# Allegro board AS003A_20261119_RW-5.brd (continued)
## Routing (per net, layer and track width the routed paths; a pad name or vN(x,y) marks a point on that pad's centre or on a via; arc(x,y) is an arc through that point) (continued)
D11006: length 247.7
  L03_DIG w0.096: D110.06 407.82,349.4 407.36,349.4 406.47,348.51 406.47,347.48 407.73,346.22 407.73,324.49 405.35,322.1 405.35,310.08 410.6,304.83 410.6,237.77 409.11,236.29 407.56,236.29 406.21,237.64 406.21,244.38 405.24,245.35 403.7,245.35 392.39,234.05 392.39,230.6 383.49,221.7 377.13,221.7 375.92,222.92 330.29,222.92 327.9,220.53 318.25,220.53 316.41,218.69 305.81,218.69 305.37,218.25 303.95,218.25 303.93,218.23 303.91,218.23
  L03_DIG w0.102: 303.91,218.23 v1(303.23,218.23)
D11007: length 228.4
  L07_DIG w0.081: D110.07 407.69,351.77 407.69,342.27 408.37,341.59 422.56,341.59 423.28,340.86 423.28,328.65 418.08,323.45 418.08,298.32 411.98,292.23 396.71,292.23 359.06,254.58 320.02,254.58 300.95,235.51 300.95,232.8 298.03,229.88 298.03,227.71
  L07_DIG w0.102: v1(297.63,223.83) 298.03,224.23 298.03,227.71
D11008: length 247.7
  L03_DIG w0.096: 303.91,218.63 303.93,218.63 303.95,218.61 305.22,218.61 305.66,219.06 316.26,219.06 318.1,220.89 327.74,220.89 330.14,223.29 376.07,223.29 377.29,222.07 383.34,222.07 392.02,230.75 392.02,234.2 403.54,245.72 405.39,245.72 406.58,244.53 406.58,237.79 407.71,236.66 408.96,236.66 410.23,237.93 410.23,304.68 404.98,309.93 404.98,322.26 407.36,324.64 407.36,346.06 406.1,347.33 406.1,348.28 D110.08
  L03_DIG w0.102: 303.91,218.63 302.83,218.63 v1(302.43,218.23)
D11009: length 204.1
  L30_DIG w0.081: 303.91,213.83 304.95,213.83 306.15,215.04 311.67,215.04 311.97,214.74 318.14,214.74 320.09,212.79 328.92,212.79 343.34,227.2 343.34,249.14 347.94,253.74 356.42,253.74 389.6,286.93 389.6,301.7 400.13,312.22 400.13,351.87 D110.09
  L30_DIG w0.102: 303.91,213.83 302.03,213.83 v1(301.63,214.23)
D11010: length 257.7
  L03_DIG w0.096: 304.3,220.65 305.64,220.65 305.87,220.42 315.54,220.42 317.14,222.03 322.45,222.03 323.87,223.45 323.87,250.58 331.92,258.63 400.22,258.63 401.32,259.73 401.32,261.39 400.09,262.62 381.07,262.62 379.92,263.77 379.92,266.18 381.22,267.48 393.73,267.48 395.4,269.15 395.4,323.41 397.65,325.66 397.65,346.01 396.45,347.22 396.45,348.84 397.11,349.5 397.76,349.5 D110.10
  L03_DIG w0.102: 304.3,220.65 304.29,220.64 304.01,220.64 304,220.63 v1(303.23,220.63)
D11011: length 200.1
  L30_DIG w0.081: 303.91,215.43 304.64,215.43 305.95,216.74 317.73,216.74 324.05,223.05 330.87,223.05 333.19,225.38 333.19,253.56 336.5,256.87 354.42,256.87 386.27,288.72 386.27,305.14 395.13,314 395.13,351.95 D110.11
  L30_DIG w0.102: 303.91,215.43 302.03,215.43 v1(301.63,215.83)
D11012: length 257.7
  L03_DIG w0.096: D110.12 396.08,348.14 396.08,347.06 397.28,345.86 397.28,325.81 395.03,323.56 395.03,269.31 393.58,267.85 381.07,267.85 379.55,266.33 379.55,263.61 380.92,262.25 399.94,262.25 400.95,261.24 400.95,259.89 400.07,259 331.77,259 323.5,250.74 323.5,223.6 322.29,222.39 316.99,222.39 315.38,220.79 306.03,220.79 305.79,221.02 304.3,221.02
  L03_DIG w0.102: 304.3,221.02 304.01,221.02 303.99,221.03 302.83,221.03 v1(302.43,220.63)
D11013: length 195.3
  L30_DIG w0.081: 303.91,217.03 304.48,217.03 305.93,218.48 316.71,218.48 322.99,224.76 322.99,254.43 328.22,259.65 352.15,259.65 383,290.5 383,307.18 389.87,314.06 389.87,351.77 D110.13
  L30_DIG w0.102: v1(301.63,217.43) 302.03,217.03 303.91,217.03
D11014: length 198.2
  L03_DIG w0.096: D110.14 387.11,349.01 387.11,347.13 386.48,346.51 378.16,346.51 375.06,343.41 375.06,270.46 365.84,261.25 331.04,261.25 320.45,250.66 320.45,239.56 321.78,238.23 321.78,233.55 320.01,231.77 320.01,226.91 315.32,222.22 305.53,222.22 305.15,221.85 303.95,221.85 303.93,221.83 303.91,221.83
  L03_DIG w0.102: v1(302.43,222.23) 302.83,221.83 303.91,221.83
D11015: length 282.4
  L30_DIG w0.081: D110.15 378.32,360.82 378.32,392.29 377.01,393.6 371.22,393.6 369.35,391.73 369.35,380.91 367.05,378.62 356.72,378.62 352.79,374.68 352.79,265.45 350.03,262.7 323,262.7 318.95,258.65 318.95,224.35 314.98,220.39 305.86,220.39 304.91,219.43 303.91,219.43
  L30_DIG w0.102: v1(301.63,219.83) 302.03,219.43 303.91,219.43
D11016: length 198.2
  L03_DIG w0.096: D110.16 384.69,349.37 386.17,349.37 386.74,348.81 386.74,347.29 386.33,346.88 378.01,346.88 374.69,343.56 374.69,270.61 365.69,261.61 330.89,261.61 320.08,250.81 320.08,239.41 321.41,238.08 321.41,233.7 319.64,231.93 319.64,227.06 315.17,222.59 305.37,222.59 305,222.21 303.95,222.21 303.93,222.23 303.91,222.23
  L03_DIG w0.102: 303.91,222.23 v1(303.23,222.23)
D11101: length 237.5
  L07_DIG w0.081: K6.4 322.29,215.85 331.17,215.85 337.56,222.24 363.64,222.24 373.56,232.16 373.56,253.87 401.82,282.13 417.05,282.13 426.22,291.3 426.22,321.09 430.41,325.28 430.41,364.61 D111.01
D11102: length 314.6
  L05_DIG w0.079: D111.02 416.55,368.29 416.55,367.75 416.98,367.33 421.46,367.33 423.64,369.51 423.64,374.16 424.78,375.3 426.45,375.3 427.4,374.35 427.4,331.64 416.59,320.82 416.59,242.73 414.27,240.41 393.3,240.41 391.5,242.22 374.81,242.22 372.2,244.83 358.67,244.83 353.56,249.94 343.4,249.94 335.86,257.48 329.99,257.48 323.46,250.95 323.46,222.67 319.41,218.62 305.7,218.62 305.12,218.04 304.14,218.04 303.93,217.83 303.91,217.83
  L05_DIG w0.102: v1(300.83,218.23) 301.23,217.83 303.91,217.83
D11103: length 257.9
  L07_DIG w0.081: 303.91,218.63 304.36,218.63 306.35,220.62 327.88,220.62 330.44,223.18 352.93,223.18 359.55,229.79 359.55,233.3 363.5,237.25 370.61,237.25 372.72,239.37 372.72,254.74 401.18,283.2 416.56,283.2 424.87,291.52 424.87,321.98 429.29,326.39 429.29,363.04 422.88,369.45 418.29,369.45 417.76,369.99 417.76,372.18 D111.03
  L07_DIG w0.102: v1(300.03,219.03) 300.43,218.63 303.91,218.63
D11104: length 314.6
  L05_DIG w0.079: D111.04 416.17,368.69 416.17,367.59 416.82,366.94 421.62,366.94 424.03,369.35 424.03,374 424.94,374.92 426.3,374.92 427.02,374.19 427.02,331.8 416.2,320.98 416.2,242.89 414.11,240.8 393.46,240.8 391.66,242.6 374.97,242.6 372.36,245.21 358.83,245.21 353.72,250.32 343.56,250.32 336.02,257.87 329.84,257.87 323.08,251.11 323.08,222.83 319.26,219 305.54,219 304.96,218.42 304.14,218.42 303.93,218.63 303.91,218.63
  L05_DIG w0.102: 303.91,218.63 300.43,218.63 v1(300.03,218.23)
D11105: length 257.7
  L07_DIG w0.081: D111.05 412.58,372.28 412.58,368.07 413.52,367.12 422.61,367.12 428.16,361.58 428.16,327 423.65,322.49 423.65,292.66 415.53,284.55 399.82,284.55 360.5,245.23 360.5,239.32 357.8,236.61 350.91,236.61 349.59,237.94 339.39,237.94 338.91,238.42 338.42,238.42 333.91,233.91 330.62,233.91 329.78,234.76 322.51,234.76 319.03,231.28 319.03,224.9 316.49,222.37 306.17,222.37 304.83,221.03 303.91,221.03
  L07_DIG w0.102: v1(300.03,221.43) 300.43,221.03 303.91,221.03
D11106: length 260.6
  L05_DIG w0.079: 303.91,220.23 303.93,220.23 304.14,220.44 316.37,220.44 319.4,223.47 319.4,250.59 330.29,261.49 411.02,261.49 412.14,262.6 412.14,267.22 411.13,268.22 405.79,268.22 405.37,268.64 405.37,366.13 406.42,367.18 406.42,368.32 D111.06
  L05_DIG w0.102: 303.91,220.23 301.23,220.23 v1(300.83,220.63)
D11107: length 233.2
  L30_DIG w0.081: D111.07 405.15,372.13 405.15,312.76 393.52,301.14 393.52,284.74 368.11,259.33 368.11,234.42 358.05,224.36 343.77,224.36 341.28,221.87 341.28,220.83 331.21,210.77 318.17,210.77 315.83,213.11 306.08,213.11 305.2,212.23 303.91,212.23
  L30_DIG w0.102: v1(301.63,212.63) 302.03,212.23 303.91,212.23
D11108: length 260.6
  L05_DIG w0.079: 303.91,221.03 303.93,221.03 304.14,220.82 316.21,220.82 319.02,223.62 319.02,250.75 330.14,261.87 410.86,261.87 411.75,262.76 411.75,267.06 410.98,267.84 405.63,267.84 404.99,268.48 404.99,366.29 406.03,367.34 406.03,368.67 D111.08
  L05_DIG w0.102: v1(300.03,220.63) 300.43,221.03 303.91,221.03
D11109: length 257.7
  L34_DIG w0.102: v1(299.23,220.63) 299.63,221.03 303.91,221.03
  L34_DIG w0.104: D111.09 400.12,372.18 400.12,325.96 411.4,314.68 411.4,241.83 406.41,236.84 393.28,236.84 380.77,224.32 377.86,224.32 377.39,223.85 332.06,223.85 330.46,222.25 306.26,222.25 305.04,221.03 303.91,221.03
D11110: length 266.2
  L05_DIG w0.079: 303.91,221.83 303.93,221.83 304.14,222.04 315.48,222.04 316.52,223.08 316.52,242.24 317.95,243.66 317.95,253.63 327.78,263.46 398.09,263.46 401.47,266.84 401.47,270.34 398.99,272.82 385.86,272.82 383.75,274.93 383.75,281.5 385.79,283.54 392.05,283.54 395.25,286.73 395.25,366.16 397.12,368.03 397.12,369.18 D111.10
  L05_DIG w0.102: 303.91,221.83 300.43,221.83 v1(300.03,222.23)
D11111: length 328.2
  L34_DIG w0.102: v1(299.23,221.43) 299.63,221.83 303.91,221.83
  L34_DIG w0.104: D111.11 394.65,371.79 394.65,326.22 400.89,319.99 400.89,263.5 402.61,261.78 405.27,261.78 406.52,263.02 406.52,295.73 407.47,296.68 408.49,296.68 409.47,295.7 409.47,243.2 404.72,238.44 392.7,238.44 380.75,226.49 360.84,226.49 359.09,224.73 331.53,224.73 330.35,223.55 317.05,223.55 316.23,222.72 306.07,222.72 305.17,221.83 303.91,221.83
D11112: length 266.2
  L05_DIG w0.079: 303.91,222.63 303.93,222.63 304.14,222.42 315.32,222.42 316.14,223.24 316.14,242.4 317.56,243.82 317.56,253.79 327.62,263.84 397.93,263.84 401.09,267 401.09,270.18 398.83,272.44 385.7,272.44 383.37,274.77 383.37,281.66 385.63,283.92 391.89,283.92 394.86,286.89 394.86,366.32 396.73,368.19 396.73,369.3 396.32,369.72 394.82,369.72 D111.12
  L05_DIG w0.102: 303.91,222.63 301.23,222.63 v1(300.83,222.23)
D11113: length 247.7
  L34_DIG w0.102: 303.91,223.03 v1(303.23,223.03)
  L34_DIG w0.104: D111.13 389.85,372.07 389.85,312.14 390.82,311.18 392.74,311.18 393.63,312.08 393.63,318.91 394.38,319.65 396.1,319.65 396.84,318.91 396.84,277.06 376.34,256.56 326.37,256.56 319.45,249.64 319.45,227.69 315.85,224.09 304.97,224.09 303.91,223.03
D11114: length 328.2
  L05_DIG w0.079: D111.14 386.1,368.32 386.1,367.48 385.47,366.85 379.1,366.85 375.47,370.48 375.47,416.09 372.26,419.3 355.21,419.3 352.39,416.48 352.39,314.44 350.57,312.62 309.19,312.62 307.71,311.14 307.71,244.16 305.37,241.82 305.37,225 304.81,224.44 304.14,224.44 303.93,224.23 303.91,224.23
  L05_DIG w0.102: v1(300.83,224.63) 301.23,224.23 303.91,224.23
D11115: length 250.4
  L34_DIG w0.102: v1(303.23,223.83) 303.91,223.83
  L34_DIG w0.104: D111.15 384.84,372.14 384.84,289.8 385.06,289.59 385.37,289.59 385.58,289.8 385.58,304.21 385.8,304.43 386.11,304.43 386.32,304.21 386.32,270.68 373.83,258.18 323.52,258.18 316.91,251.57 316.91,227.55 315.28,225.93 306.01,225.93 303.91,223.83
D11116: length 328.2
  L05_DIG w0.079: D111.16 385.71,368.67 385.71,367.64 385.31,367.23 379.26,367.23 375.86,370.64 375.86,416.25 372.42,419.68 355.05,419.68 352.01,416.64 352.01,314.6 350.41,313 309.03,313 307.33,311.3 307.33,244.32 304.98,241.98 304.98,225.16 304.65,224.82 304.14,224.82 303.93,225.03 303.91,225.03
  L05_DIG w0.102: v1(300.03,224.63) 300.43,225.03 303.91,225.03
D11201: length 279.5
  L05_DIG w0.079: v1(333.87,244.93) 334.39,244.93 334.56,245.1 334.56,245.46 334.34,245.68 333.49,245.68 333.14,245.33 333.14,243.58 334.45,242.26 340.27,242.26 345.32,237.22 345.32,235.62 348.36,232.57 375.92,232.57 376.85,233.5 390.64,233.5 394.73,237.59 418.18,237.59 424.06,243.47 424.06,323.09 429.02,328.06 429.02,392.05 423.47,397.61 420.22,397.61 418.38,395.77 418.38,394.98 418.52,394.85 420.49,394.85 D112.01
  BOTTOM w0.109: v1(333.87,244.93) 333.87,242.8 333.56,242.38 333.13,242.32 K2.6
D11202: length 289.9
  L30_DIG w0.081: 303.91,207.43 304.94,207.43 305.31,207.8 313.47,207.8 317.73,203.54 389.67,203.54 404.9,218.76 404.9,297.48 417.74,310.33 417.74,389.8 D112.02
  L30_DIG w0.102: 303.91,207.43 302.03,207.43 v1(301.63,207.83)
D11203: length 279.5
  L05_DIG w0.079: v1(333.87,246.82) 333.87,246.22 333.71,246.06 333.33,246.06 332.75,245.48 332.75,243.42 334.29,241.88 340.11,241.88 344.93,237.06 344.93,235.46 348.2,232.19 376.08,232.19 377.01,233.12 390.8,233.12 394.89,237.21 418.34,237.21 424.44,243.31 424.44,322.93 429.41,327.9 429.41,392.21 423.62,398 420.06,398 418,395.93 418,395.14 D112.03
  BOTTOM w0.109: v1(333.87,246.82) 333.87,248.95 333.56,249.37 333.13,249.43 K2.4
D11204: length 262.3
  L30_DIG w0.081: 303.91,209.83 313.83,209.83 316.9,206.76 340.81,206.76 354.1,220.06 365.92,220.06 375,229.14 375,259.03 400.26,284.29 400.26,297.92 412.76,310.42 412.76,389.9 D112.04
  L30_DIG w0.102: 303.91,209.83 302.03,209.83 v1(301.63,210.23)
D11205: length 315.5
  L05_DIG w0.079: v1(333.87,227.66) 334.46,227.66 334.59,227.79 334.59,228.29 334.48,228.41 333.49,228.41 333.19,228.1 333.19,225.87 334.67,224.39 360.29,224.39 367.97,216.71 418.03,216.71 427.4,226.08 427.4,310.62 426.01,312.02 426.01,320.93 433.02,327.94 433.02,391.55 424.81,399.76 411.95,399.76 408.19,396 408.19,395.29 408.6,394.88 410.3,394.88 D112.05
  BOTTOM w0.109: v1(333.87,227.66) 333.87,225.52 333.56,225.11 333.13,225.05 K1.6
D11206: length 255.2
  L30_DIG w0.081: D112.06 407.61,389.83 407.61,312.4 395.85,300.63 395.85,285.08 371.22,260.45 371.22,231.36 363.14,223.29 350.16,223.29 344,217.12 340.05,217.12 332.86,209.94 317.34,209.94 315.24,212.04 305.68,212.04 305.07,211.43 303.91,211.43
  L30_DIG w0.102: 303.91,211.43 302.03,211.43 v1(301.63,211.83)
D11207: length 315.5
  L05_DIG w0.079: D112.07 407.8,395.1 407.8,396.16 411.79,400.14 424.97,400.14 433.4,391.71 433.4,327.78 426.39,320.77 426.39,312.18 427.79,310.78 427.79,225.92 418.19,216.33 367.81,216.33 360.13,224.01 334.51,224.01 332.8,225.71 332.8,228.26 333.33,228.79 333.71,228.79 333.87,228.95 v1(333.87,229.54)
  BOTTOM w0.109: K1.4 333.13,232.15 333.56,232.09 333.87,231.68 v1(333.87,229.54)
D11208: length 245.4
  L30_DIG w0.081: 303.91,213.03 305.07,213.03 305.86,213.82 317.77,213.82 319.71,211.88 329.87,211.88 343.33,225.34 353.44,225.34 360.64,232.53 360.64,255.48 391.33,286.17 391.33,300.93 402.67,312.27 402.67,389.97 D112.08
  L30_DIG w0.102: v1(301.63,213.43) 302.03,213.03 303.91,213.03
D11209: length 240.3
  L32_DIG w0.081: 298.83,227.71 298.83,228.45 297.67,229.61 297.67,233.29 321.69,257.31 371.55,257.31 400.12,285.88 400.12,392.5 D112.09
  L32_DIG w0.102: 298.83,227.71 298.83,226.63 v1(298.43,226.23)
D11210: length 242.8
  L30_DIG w0.081: 303.91,214.63 304.82,214.63 305.78,215.59 318.31,215.59 318.79,216.07 329.71,216.07 334.25,220.61 334.25,251.86 338.13,255.74 355.56,255.74 387.89,288.07 387.89,303.88 397.6,313.59 397.6,389.98 D112.10
  L30_DIG w0.102: 303.91,214.63 302.03,214.63 v1(301.63,215.03)
D11211: length 240.5
  L32_DIG w0.081: 297.23,227.71 297.23,228.19 296.67,228.75 296.67,234.46 320.69,258.47 368.88,258.47 394.94,284.53 394.94,392.4 D112.11
  L32_DIG w0.102: 297.23,227.71 297.23,223.43 v1(297.63,223.03)
D11212: length 235.4
  L30_DIG w0.081: 303.91,216.23 304.37,216.23 305.54,217.4 316.95,217.4 324.16,224.61 324.16,253.17 329.14,258.15 352.84,258.15 384.9,290.2 384.9,306.31 392.47,313.89 392.47,389.93 D112.12
  L30_DIG w0.102: v1(301.63,216.63) 302.03,216.23 303.91,216.23
D11213: length 221.4
  L32_DIG w0.081: K3.4 313.82,259.71 364.64,259.71 389.93,284.99 389.93,392.47 D112.13
D11214: length 232.6
  L30_DIG w0.081: D112.14 387.58,390.12 387.58,314.38 381.35,308.15 381.35,291.64 351.23,261.52 323.78,261.52 319.94,257.68 319.94,223.7 315.43,219.19 305.54,219.19 304.98,218.63 303.91,218.63
  L30_DIG w0.102: v1(301.63,219.03) 302.03,218.63 303.91,218.63
D11215: length 230.1
  L32_DIG w0.081: D112.15 384.96,392.58 384.96,284.65 361.43,261.13 299.88,261.13 290.55,251.79 290.55,247.48 K4.4
D11216: length 244
  L32_DIG w0.081: D112.16 379.54,387.16 379.54,284.48 357.15,262.09 294.42,262.09 283.15,250.82 283.15,239.87 284.43,238.59 284.43,227.71
  L32_DIG w0.102: v1(284.03,226.23) 284.43,226.63 284.43,227.71
D11301: length 153
  L09_DIG w0.079: v3(268.73,275.54) 268.73,276.96 268.57,277.11 268.19,277.11 267.67,277.63 267.67,304.83 265.93,306.57 265.93,315.86 271.22,321.15 283.54,321.15 287.45,325.06 350.15,325.06 352.23,327.15 352.23,334.68 350.48,336.43 346.6,336.43 345.33,335.15 345.33,334.73 346.2,333.86 346.86,333.86 D113.01
  BOTTOM w0.117: R144.2 v3(268.73,275.54)
D11302: length 157.1
  L07_DIG w0.079: v3(281.85,275.54) 281.85,276.96 282.01,277.11 282.39,277.11 283.04,277.76 283.04,297 267.15,312.89 261.01,312.89 259.88,314.02 259.88,316.02 260.73,316.87 275.27,316.87 284.01,308.13 328.97,308.13 343.1,322.25 343.1,327.86 D113.02
  BOTTOM w0.117: R138.2 v3(281.85,275.54)
D11303: length 153
  L09_DIG w0.079: D113.03 344.95,334.79 344.95,335.31 346.44,336.81 350.64,336.81 352.61,334.84 352.61,326.99 350.31,324.68 287.61,324.68 283.7,320.77 271.38,320.77 266.32,315.7 266.32,306.73 268.06,304.99 268.06,277.79 268.35,277.5 268.57,277.5 268.73,277.65 v3(268.73,279.06)
  BOTTOM w0.117: R143.2 v3(268.73,279.06)
D11304: length 157.1
  L07_DIG w0.079: v3(281.85,279.06) 281.85,277.65 282.01,277.5 282.23,277.5 282.65,277.92 282.65,296.84 266.99,312.5 260.85,312.5 259.5,313.86 259.5,316.18 260.57,317.25 275.43,317.25 284.17,308.51 328.81,308.51 342.72,322.41 342.72,328.92 342.42,329.22 341.34,329.22 D113.04
  BOTTOM w0.117: R137.2 v3(281.85,279.06)
D11305: length 153
  L09_DIG w0.079: v3(283.97,275.54) 283.97,276.96 283.81,277.11 283.43,277.11 282.8,277.74 282.8,312.9 292.75,322.85 351.48,322.85 354.94,326.31 354.94,336.57 352.79,338.72 338.38,338.72 335.29,335.63 335.29,334.45 335.98,333.76 336.8,333.76 D113.05
  BOTTOM w0.117: R140.2 v3(283.97,275.54)
D11306: length 157.1
  L07_DIG w0.079: v3(266.61,275.54) 266.61,276.96 266.77,277.11 267.15,277.11 267.75,277.71 267.75,298.25 255.62,310.38 249.65,310.38 247.38,312.65 247.38,317.08 249.18,318.88 279.41,318.88 287.03,311.26 320.68,311.26 332.93,323.52 332.93,327.85 D113.06
  BOTTOM w0.117: R141.2 v3(266.61,275.54)
D11307: length 153
  L09_DIG w0.079: v3(283.97,279.06) 283.97,277.65 283.81,277.5 283.59,277.5 283.18,277.9 283.18,312.74 292.91,322.47 351.63,322.47 355.32,326.15 355.32,336.73 352.95,339.1 338.22,339.1 334.91,335.79 334.91,334.91 D113.07
  BOTTOM w0.117: R139.2 v3(283.97,279.06)
D11308: length 157.1
  L07_DIG w0.079: v3(266.61,279.06) 266.61,277.65 266.77,277.5 266.99,277.5 267.36,277.87 267.36,298.09 255.46,309.99 249.5,309.99 247,312.49 247,317.24 249.02,319.26 279.57,319.26 287.19,311.65 320.52,311.65 332.55,323.68 332.55,328.93 332.22,329.25 331.15,329.25 D113.08
  BOTTOM w0.117: R142.2 v3(266.61,279.06)
D11309: length 153
  L09_DIG w0.079: D113.09 326.4,334 326.4,334.89 322.12,339.17 288.4,339.17 274.36,325.13 240.48,325.13 231.8,316.45 231.8,302.58 237.21,297.17 237.21,277.61 237.71,277.11 238.09,277.11 238.25,276.96 v3(238.25,275.54)
  BOTTOM w0.117: R152.2 v3(238.25,275.54)
D11310: length 157.1
  L07_DIG w0.079: D113.10 322.77,327.85 322.77,326.24 318.32,321.79 235.61,321.79 232.38,318.56 232.38,310.85 235.57,307.67 245.41,307.67 252.55,300.52 252.55,277.75 251.91,277.11 251.53,277.11 251.37,276.96 v3(251.37,275.54)
  BOTTOM w0.117: R145.2 v3(251.37,275.54)
D11311: length 153
  L09_DIG w0.079: D113.11 323.98,334.14 325.69,334.14 326.01,334.46 326.01,334.73 321.96,338.79 288.56,338.79 274.52,324.75 240.64,324.75 232.19,316.29 232.19,302.74 237.6,297.33 237.6,277.77 237.87,277.5 238.09,277.5 238.25,277.65 v3(238.25,279.06)
  BOTTOM w0.117: R151.2 v3(238.25,279.06)
D11312: length 157.1
  L07_DIG w0.079: D113.12 321.08,329.16 322.17,329.16 322.39,328.94 322.39,326.4 318.16,322.17 235.46,322.17 232,318.71 232,310.69 235.41,307.28 245.25,307.28 252.16,300.37 252.16,277.91 251.75,277.5 251.53,277.5 251.37,277.65 v3(251.37,279.06)
  BOTTOM w0.117: R146.2 v3(251.37,279.06)
D11313: length 153
  L09_DIG w0.079: D113.13 316.02,334.22 316.02,335.17 314.35,336.84 292.11,336.84 278.68,323.41 240.91,323.41 233.39,315.9 233.39,303.73 235.4,301.72 249.58,301.72 252.36,298.94 252.36,277.7 252.95,277.11 253.33,277.11 253.49,276.96 v3(253.49,275.54)
  BOTTOM w0.117: R148.2 v3(253.49,275.54)
D11314: length 157.1
  L07_DIG w0.079: v3(236.13,275.54) 236.13,276.96 236.29,277.11 236.67,277.11 237.23,277.67 237.23,297.77 231.25,303.75 223.94,303.75 220.49,307.21 220.49,320.11 224.26,323.88 310.73,323.88 312.88,326.03 312.88,328.12 D113.14
  BOTTOM w0.117: R149.2 v3(236.13,275.54)
D11315: length 153
  L09_DIG w0.079: v3(253.49,279.06) 253.49,277.65 253.33,277.5 253.11,277.5 252.75,277.86 252.75,299.1 249.74,302.1 235.56,302.1 233.77,303.89 233.77,315.74 241.06,323.03 278.84,323.03 292.27,336.46 314.19,336.46 315.63,335.01 315.63,333.92 315.39,333.68 313.36,333.68 D113.15
  BOTTOM w0.117: R147.2 v3(253.49,279.06)
D11316: length 157.1
  L07_DIG w0.079: D113.16 310.9,329.18 311.63,329.18 312.49,328.31 312.49,326.19 310.57,324.27 224.1,324.27 220.1,320.27 220.1,307.05 223.78,303.37 231.09,303.37 236.84,297.61 236.84,277.83 236.51,277.5 236.29,277.5 236.13,277.65 v3(236.13,279.06)
  BOTTOM w0.117: R150.2 v3(236.13,279.06)
D11401: length 247.7
  L30_DIG w0.081: 303.91,221.03 305.11,221.03 307.26,223.18 307.26,229.05 306.36,229.96 306.36,239.27 307.72,240.63 307.72,289.39 311.23,292.91 347.04,292.91 347.29,292.66 347.29,292.36 347.11,292.19 313.72,292.19 313.51,291.98 313.51,291.68 313.72,291.47 347.81,291.47 349.31,292.98 349.31,325.48 346.75,328.05 346.75,351.83 D114.01
  L30_DIG w0.102: 303.91,221.03 302.03,221.03 v1(301.63,221.43)
D11402: length 282.4
  L03_DIG w0.096: 303.91,224.63 303.93,224.63 303.95,224.65 304.78,224.65 305.4,224.03 315.37,224.03 316.97,225.62 316.97,232.24 319.09,234.37 319.09,254.24 327.75,262.9 346.9,262.9 353.69,269.68 353.69,299.79 364.03,310.13 364.03,362.85 370.14,368.96 370.14,386.57 366.27,390.45 355.79,390.45 352.05,386.71 352.05,348.88 349.99,346.81 343.74,346.81 343.14,347.41 343.14,348.87 343.66,349.4 344.32,349.4 D114.02
  L03_DIG w0.102: 303.91,224.63 v1(303.23,224.63)
D11403: length 250.4
  L30_DIG w0.081: 303.91,223.43 304.75,224.27 304.75,290.55 312.06,297.86 330.92,297.86 331.13,297.65 331.13,297.36 330.92,297.15 315.03,297.15 314.83,296.95 314.83,296.65 315.05,296.43 341.35,296.43 343.76,298.84 343.76,322.12 343.97,322.33 344.27,322.33 344.48,322.12 344.48,299.1 344.68,298.9 344.98,298.9 345.19,299.12 345.19,322.74 341.73,326.2 341.73,351.89 D114.03
  L30_DIG w0.102: v1(301.63,223.83) 302.03,223.43 303.91,223.43
D11404: length 282.4
  L03_DIG w0.096: 303.91,225.03 303.93,225.03 303.95,225.01 304.93,225.01 305.55,224.39 315.22,224.39 316.6,225.77 316.6,232.4 318.72,234.52 318.72,254.39 327.59,263.26 346.75,263.26 353.32,269.83 353.32,299.94 363.67,310.29 363.67,363 369.77,369.11 369.77,386.42 366.12,390.08 355.95,390.08 352.42,386.55 352.42,348.72 350.14,346.44 343.59,346.44 342.77,347.26 342.77,348.11 D114.04
  L03_DIG w0.102: 303.91,225.03 302.83,225.03 v1(302.43,224.63)
D11405: length 234.1
  L30_DIG w0.081: 301.23,227.71 301.23,254.17 302.84,255.78 302.84,291.85 311.85,300.86 339.69,300.86 341.4,302.57 341.4,321.84 340.89,322.35 340.23,322.35 339.88,322 339.88,303.24 339.34,302.71 338.58,302.71 338.12,303.16 338.12,320.8 337.91,321.01 337.61,321.01 337.4,320.8 337.4,305.97 337.2,305.76 336.9,305.76 336.69,305.97 336.69,351.93 D114.05
  L30_DIG w0.102: 301.23,227.71 301.23,225.83 v1(301.63,225.43)
D11406: length 234.1
  L03_DIG w0.096: D114.06 333.71,348.95 333.71,346.65 334.16,346.21 334.16,326.23 335.89,324.49 337.7,324.49 339.5,322.69 339.5,319.68 338.31,318.49 315.57,318.49 314.67,317.59 314.67,315.51 315.48,314.69 360.56,314.69 361.85,313.4 361.85,311.29 360.1,309.54 352.23,309.54 338.81,296.11 338.81,275.2 332.39,268.79 323.8,268.79 305.49,250.47 305.49,226.56 304.78,225.85 303.95,225.85 303.93,225.83 303.91,225.83
  L03_DIG w0.102: v1(302.43,226.23) 302.83,225.83 303.91,225.83
D11407: length 198.2
  L30_DIG w0.081: 298.83,227.71 298.83,230.48 297.62,231.69 297.62,272.73 294.03,276.33 294.03,289.99 310.02,305.98 329.42,305.98 329.63,305.77 329.63,305.47 329.42,305.26 310.8,305.26 310.57,305.04 310.57,304.74 310.77,304.55 330.36,304.55 331.56,305.74 331.56,351.88 D114.07
  L30_DIG w0.102: 298.83,227.71 298.83,225.83 v1(299.23,225.43)
D11408: length 234.1
  L03_DIG w0.096: 303.91,226.23 303.93,226.23 303.95,226.21 304.63,226.21 305.12,226.71 305.12,250.63 323.65,269.15 332.24,269.15 338.44,275.36 338.44,296.27 352.08,309.91 359.95,309.91 361.48,311.44 361.48,313.24 360.4,314.32 315.33,314.32 314.3,315.35 314.3,317.74 315.42,318.86 338.16,318.86 339.13,319.83 339.13,322.54 337.54,324.12 335.74,324.12 333.79,326.08 333.79,346.06 333.35,346.5 333.35,348.92 332.91,349.35 331.37,349.35 D114.08
  L03_DIG w0.102: 303.91,226.23 v1(303.23,226.23)
D11409: length 149.7
  L30_DIG w0.081: 283.63,227.71 283.63,230.5 290.15,237.03 290.15,292.51 306.79,309.14 313.13,309.14 326.41,322.43 326.41,351.81 D114.09
  L30_DIG w0.102: 283.63,227.71 283.63,225.83 v1(284.03,225.43)
D11410: length 250.4
  L03_DIG w0.096: 301.23,227.71 301.23,227.73 301.01,227.95 301.01,251.58 305.26,255.82 305.26,291.03 306.73,292.5 332.65,292.5 333.81,293.67 333.81,296.71 332.11,298.41 297.82,298.41 296.21,300.01 296.21,303.25 297.89,304.92 330.15,304.92 333.57,308.35 333.57,310.71 331.81,312.48 314.83,312.48 312.25,315.06 312.25,318.03 315.4,321.19 317.87,321.19 321.51,324.84 321.51,345.94 323.59,348.02 323.59,348.99 D114.10
  L03_DIG w0.102: 301.23,227.71 301.23,225.95 301.11,225.83 300.43,225.83 v1(300.03,226.23)
D11411: length 206.2
  L30_DIG w0.081: 282.03,227.71 282.03,232.19 287.77,237.93 287.77,296.96 283.37,301.37 283.37,337.38 286.14,340.14 297.43,340.14 300.29,337.29 300.29,322.33 305.51,317.1 314.55,317.1 321.41,323.96 321.41,351.89 D114.11
  L30_DIG w0.102: v1(282.43,225.43) 282.03,225.83 282.03,227.71
D11412: length 250.4
  L03_DIG w0.096: D114.12 321.22,349.34 322.66,349.34 323.22,348.77 323.22,348.17 321.15,346.09 321.15,324.99 317.71,321.56 315.25,321.56 311.88,318.19 311.88,314.91 314.68,312.11 331.65,312.11 333.21,310.56 333.21,308.5 330,305.29 297.74,305.29 295.85,303.4 295.85,299.86 297.67,298.04 331.96,298.04 333.44,296.55 333.44,293.82 332.5,292.87 306.58,292.87 304.89,291.19 304.89,255.98 300.65,251.73 300.65,227.95 300.43,227.73 300.43,227.71
  L03_DIG w0.102: v1(300.83,226.23) 300.43,226.63 300.43,227.71
D11413: length 515.3
  L30_DIG w0.081: D114.13 316.48,352.04 316.48,325.37 310.95,319.85 307.56,319.85 304.72,322.68 304.72,347.76 299.15,353.33 299.15,402.5 293.59,408.06 293.59,417.8 292.67,418.72 279.94,418.72 279.52,419.15 279.52,420.08 280.03,420.6 295.42,420.6 295.92,421.09 295.92,421.85 295.15,422.62 247.15,422.62 246.82,422.28 246.82,420.8 247.1,420.52 276.31,420.52 276.53,420.3 276.53,420 276.33,419.8 247.45,419.8 247.25,419.61 247.25,419.31 247.47,419.08 277.86,419.08 280.65,416.3 280.65,298.9 283.01,296.54 283.01,236.15 279.63,232.77 279.63,227.71
  L30_DIG w0.102: 279.63,227.71 279.63,225.83 v1(280.03,225.43)
D11414: length 515.2
  L03_DIG w0.096: 281.82,228.21 281.82,232.74 289.28,240.2 289.28,320.41 277.56,332.12 277.56,420.88 282.39,425.7 299.23,425.7 304.73,420.2 304.73,409.03 301.25,405.56 281.34,405.56 279.82,404.04 279.82,401.1 281.04,399.89 302.27,399.89 303.72,398.44 303.72,394.79 302.2,393.28 282.15,393.28 280.97,392.09 280.97,334.12 282.42,332.67 284.72,332.67 286.07,334.02 286.07,386.8 287.51,388.25 291.41,388.25 292.85,386.8 292.85,350.28 296.68,346.46 311.71,346.46 312.62,347.37 312.62,348.18 D114.14
  L03_DIG w0.102: v1(281.63,226.23) 282.03,226.63 282.03,227.71 281.82,227.92 281.82,228.21
D11415: length 394.1
  L30_DIG w0.081: 277.75,223.57 277.24,224.08 277.24,413.89 274.92,416.2 232.57,416.2 230.14,418.63 230.14,422.62 232.83,425.31 299.32,425.31 304.15,420.48 304.15,361.33 D114.15
  L30_DIG w0.102: v1(280.03,223.83) 279.63,223.43 277.89,223.43 277.75,223.57
D11416: length 515.3
  L03_DIG w0.096: 281.45,228.21 281.45,232.89 288.91,240.35 288.91,320.26 277.19,331.97 277.19,421.03 282.24,426.07 299.38,426.07 305.1,420.36 305.1,408.88 301.41,405.19 281.5,405.19 280.19,403.89 280.19,401.26 281.19,400.26 302.42,400.26 304.09,398.59 304.09,394.64 302.35,392.91 282.31,392.91 281.34,391.94 281.34,334.27 282.58,333.03 284.57,333.03 285.7,334.17 285.7,386.95 287.36,388.61 291.56,388.61 293.22,386.95 293.22,350.44 296.83,346.82 311.56,346.82 312.26,347.52 312.26,348.14 D114.16
  L03_DIG w0.102: 281.45,228.21 281.44,228.2 281.44,227.92 281.23,227.71 281.23,226.63 v1(280.83,226.23)
D11501: length 198.2
  L34_DIG w0.102: v1(300.83,227.03) 300.83,227.71
  L34_DIG w0.104: D115.01 346.8,372.2 346.8,307.24 347.04,307.01 347.34,307.01 347.54,307.21 347.54,312.94 347.76,313.16 348.07,313.16 348.28,312.94 348.28,298.76 342.03,292.51 310.5,292.51 307.47,289.47 307.47,259.51 300.83,252.87 300.83,227.71
D11502: length 247.7
  L30_DIG w0.081: 303.91,222.63 304.13,222.63 305.55,224.05 305.55,243.58 306.72,244.75 306.72,289.75 310.8,293.84 342.87,293.84 343.08,294.05 343.08,294.34 342.87,294.55 313.83,294.55 313.63,294.75 313.63,295.05 313.85,295.27 343.08,295.27 347.06,299.25 347.06,324.16 344.21,327.01 344.21,369.61 D115.02
  L30_DIG w0.102: 303.91,222.63 302.03,222.63 v1(301.63,223.03)
D11503: length 198.2
  L34_DIG w0.102: v1(299.23,227.03) 299.23,227.71
  L34_DIG w0.104: 299.23,227.71 299.23,229.8 297.54,231.49 297.54,258.69 303.74,264.9 303.74,294.35 307.02,297.62 334.43,297.62 343.11,306.3 343.11,315.4 342.89,315.62 342.59,315.62 342.37,315.4 342.37,308.44 342.17,308.24 341.87,308.24 341.63,308.47 341.63,372.11 D115.03
D11504: length 250.4
  L30_DIG w0.081: D115.04 341.32,371.8 341.32,373.97 342.17,374.81 344.66,374.81 348.21,378.36 348.21,378.93 347.56,379.58 342.09,379.58 341.71,379.96 341.71,381.41 342.38,382.09 353.66,382.09 354.26,382.7 354.26,384.31 353.54,385.04 339.67,385.04 339.2,384.58 339.2,325.3 342.57,321.93 342.57,299.86 340.61,297.9 332.92,297.9 331.33,299.48 312.01,299.48 303.91,291.38 303.91,227.71
  L30_DIG w0.102: 303.91,227.71 303.91,224.57 303.57,224.23 302.03,224.23 v1(301.63,224.63)
D11505: length 181.2
  L34_DIG w0.102: 284.03,227.71 v1(284.03,227.03)
  L34_DIG w0.104: 284.03,227.71 284.03,231.18 290.8,237.95 290.8,252.47 292.03,253.7 292.03,297.88 295.92,301.77 317.29,301.77 336.58,321.06 336.58,372.14 D115.05
D11506: length 266.2
  L30_DIG w0.081: D115.06 336.34,371.9 336.34,385.63 335.98,385.98 334.83,385.98 334.35,385.5 334.35,311.36 334.14,311.15 333.84,311.15 333.63,311.36 333.63,320.03 333.42,320.24 333.13,320.24 332.92,320.03 332.92,308.65 333.97,307.59 333.97,303.96 331.92,301.91 313.12,301.91 312.94,302.08 312.94,302.38 313.19,302.62 331.37,302.62 331.58,302.83 331.58,303.13 331.37,303.34 311.85,303.34 298.74,290.23 298.74,282.15 301.51,279.38 301.51,275.56 299.05,273.09 299.05,264.44 300.18,263.3 300.18,228.97 299.63,228.42 299.63,227.71
  L30_DIG w0.102: v1(300.03,225.43) 299.63,225.83 299.63,227.71
D11507: length 178.8
  L32_DIG w0.081: 283.63,227.71 283.63,235.41 279.65,239.39 279.65,250.82 292.8,263.96 292.8,294.06 300.43,301.69 313.79,301.69 331.58,319.48 331.58,372.22 D115.07
  L32_DIG w0.102: 283.63,227.71 283.63,226.63 v1(283.23,226.23)
D11508: length 167.2
  L30_DIG w0.081: D115.08 329.03,369.67 329.03,320.99 315.54,307.51 308.85,307.51 292.79,291.45 292.79,275.7 294.2,274.29 294.2,233.02 298.03,229.2 298.03,227.71
  L30_DIG w0.102: v1(298.43,225.43) 298.03,225.83 298.03,227.71
D11509: length 369.7
  L32_DIG w0.081: 282.03,227.71 282.03,232.18 277.91,236.3 277.91,251.45 289.04,262.57 289.04,371.24 289.98,372.17 291.33,372.17 292.69,370.8 292.69,330.07 293.97,328.79 296.68,328.79 297.55,329.66 297.55,371.26 298.55,372.26 301.01,372.26 302.14,371.13 302.14,328.45 306.16,324.43 324.3,324.43 326.46,326.59 326.46,372.18 D115.09
  L32_DIG w0.102: v1(282.43,223.03) 282.03,223.43 282.03,227.71
D11510: length 414.8
  L05_DIG w0.079: D115.10 323.96,369.68 322.89,369.68 321.78,368.57 321.78,366.37 321.44,366.03 321.44,326.14 320.11,324.81 307.17,324.81 306.47,324.11 306.47,322.88 307.36,321.99 346.4,321.99 348.45,319.94 348.45,317.5 347.11,316.16 305.94,316.16 301.65,320.45 301.65,326.88 298.82,329.71 293.16,329.71 291.57,328.11 291.57,315.59 289.97,314 287.38,314 285.53,315.84 285.53,370.67 284.2,372.01 282.78,372.01 281.69,370.92 281.69,311.7 288.81,304.59 288.81,240.58 276.8,228.57 276.8,225.16 277.13,224.83 277.35,224.83
  L05_DIG w0.102: 277.35,224.83 277.64,224.83 277.84,225.03 280.43,225.03 v1(280.83,224.63)
D11511: length 169.5
  L30_DIG w0.081: 282.83,227.71 282.83,231.34 288.96,237.47 288.96,293.98 305.41,310.43 311.9,310.43 323.97,322.5 323.97,371.99 D115.11
  L30_DIG w0.102: v1(283.23,225.43) 282.83,225.83 282.83,227.71
D11512: length 414.8
  L05_DIG w0.079: D115.12 321.39,369.49 321.39,366.53 321.06,366.19 321.06,326.3 319.95,325.2 307.01,325.2 306.08,324.27 306.08,322.72 307.2,321.6 346.24,321.6 348.07,319.78 348.07,317.65 346.95,316.54 306.1,316.54 302.03,320.61 302.03,327.04 298.98,330.09 293.01,330.09 291.18,328.27 291.18,315.75 289.81,314.38 287.54,314.38 285.92,316 285.92,370.83 284.36,372.39 282.62,372.39 281.31,371.08 281.31,311.54 288.42,304.43 288.42,240.74 276.42,228.73 276.42,225 276.97,224.44 277.35,224.44
  L05_DIG w0.102: v1(281.63,224.63) 281.23,224.23 277.85,224.23 277.65,224.42 277.36,224.42 277.35,224.44
D11513: length 378.6
  L30_DIG w0.081: D115.13 318.84,372.04 318.84,324.72 312.52,318.4 306.27,318.4 302.22,322.45 302.22,346.79 296.96,352.05 296.96,401.71 289.99,408.68 289.99,414.08 291.29,415.38 291.82,415.38 292.17,415.73 292.17,416.66 291.76,417.07 282.44,417.07 281.53,416.16 281.53,300.28 283.92,297.88 283.92,282.04 285.94,280.03 285.94,274.04 284,272.1 284,265.21 286.59,262.62 286.59,238.29 281.23,232.92 281.23,227.71
  L30_DIG w0.102: v1(281.63,225.43) 281.23,225.83 281.23,227.71
D11514: length 206.2
  L05_DIG w0.079: 277.63,222.43 276.72,222.43 276.12,223.03 273.33,223.03 272.66,223.69 272.66,227.41 278.59,233.34 278.59,372.19 284.35,377.94 292.06,377.94 303.16,366.85 311.91,366.85 312.77,367.71 312.77,368.65 D115.14
  L05_DIG w0.102: 277.63,222.43 277.91,222.43 278.11,222.63 281.23,222.63 v1(281.63,222.23)
D11515: length 394.1
  L30_DIG w0.081: 278.12,227.71 278.56,228.15 278.56,414.43 275.41,417.58 245.89,417.58 244.55,418.92 244.55,422.09 246.14,423.69 295.61,423.69 302.8,416.5 302.8,352.86 306.6,349.06 312.56,349.06 313.78,350.29 313.78,372.02 D115.15
  L30_DIG w0.102: v1(280.03,224.63) 279.63,224.23 278.09,224.23 277.75,224.57 277.75,227.34 278.12,227.71
D11516: length 206.2
  L05_DIG w0.079: D115.16 312.39,368.33 312.39,367.87 311.75,367.23 303.31,367.23 292.22,378.33 284.19,378.33 278.21,372.35 278.21,233.5 272.28,227.57 272.28,223.54 273.17,222.65 275.96,222.65 276.56,222.05 277.63,222.05
  L05_DIG w0.102: v1(280.83,222.23) 280.43,221.83 278.11,221.83 277.91,222.03 277.65,222.03 277.63,222.05
D11601:
  vias: v1(182.61,297.94) v1(182.61,295.15)
D11602: length 198.2
  L34_DIG w0.102: 300.03,227.71 v1(300.03,227.03)
  L34_DIG w0.104: 300.03,227.71 300.03,257.34 304.71,262.02 304.71,291.06 307.84,294.19 333.95,294.19 344.08,304.32 344.08,389.8 D116.02
D11603: length 234.1
  L34_DIG w0.102: 302.43,227.71 v1(302.43,227.03)
  L34_DIG w0.104: 302.43,227.71 302.43,244.94 320.18,262.69 346.97,262.69 352.9,268.62 352.9,299.2 354.68,300.97 354.68,378.14 356.16,379.62 356.16,391.12 355.94,391.33 355.64,391.33 355.42,391.12 355.42,383.47 355.23,383.27 354.92,383.27 354.68,383.51 354.68,392.87 352.5,395.05 344.25,395.05 D116.03
D11604: length 195
  L34_DIG w0.102: 298.43,227.71 v1(298.43,227.03)
  L34_DIG w0.104: 298.43,227.71 298.43,229.53 294.11,233.85 294.11,260.23 298.41,264.53 298.41,296.3 301.68,299.57 318.59,299.57 339.24,320.23 339.24,390.04 D116.04
D11605: length 234.1
  L34_DIG w0.102: 303.23,227.71 v1(303.23,227.03)
  L34_DIG w0.104: 303.23,227.71 303.23,243.03 319.62,259.42 347.3,259.42 355.31,267.44 355.31,297.72 357.79,300.19 357.79,374.9 362,379.11 362,392.86 357.28,397.58 341.7,397.58 D116.05
D11606: length 198.4
  L34_DIG w0.102: 283.23,227.71 v1(283.23,227.03)
  L34_DIG w0.104: 283.23,227.71 283.23,231.98 289.61,238.36 289.61,298.88 294.91,304.19 316.68,304.19 333.99,321.5 333.99,389.87 D116.06
D11607: length 206.2
  L34_DIG w0.102: v1(282.43,227.03) 282.43,227.71
  L34_DIG w0.104: 282.43,227.71 282.43,232.75 288.07,238.39 288.07,298.17 286.14,300.11 286.14,362.21 301.42,377.49 330.66,377.49 331.4,378.23 331.4,392.36 D116.07
D11608: length 206.2
  L34_DIG w0.102: v1(281.63,227.03) 281.63,227.71
  L34_DIG w0.104: D116.08 328.91,389.87 328.91,380.65 327.86,379.59 294.49,379.59 283.27,368.37 283.27,253.59 286.2,250.66 286.2,237.81 281.63,233.25 281.63,227.71
D11609: length 206.2
  L34_DIG w0.102: v1(280.83,227.03) 280.83,227.71
  L34_DIG w0.104: 280.83,227.71 280.83,233.54 282.99,235.71 282.99,250.73 278.83,254.89 278.83,368.13 295.73,385.03 324.3,385.03 326.36,387.09 326.36,392.4 D116.09
D11610: length 234.1
  L34_DIG w0.102: 301.63,227.71 v1(301.63,227.03)
  L34_DIG w0.104: D116.10 323.99,392.29 323.99,394.38 324.84,395.22 335.61,395.22 336.39,394.44 336.39,393.2 337.17,392.43 348.81,392.43 350.95,390.29 350.95,298.43 343.98,291.46 315.51,291.46 313.76,289.71 313.76,260.94 301.63,248.81 301.63,227.71
D11611: length 328.2
  L32_DIG w0.081: D116.11 324.01,395.13 404.12,395.13 405.21,394.04 405.21,286.26 374.96,256 324.39,256 299.63,231.25 299.63,227.71
  L32_DIG w0.102: v1(299.23,223.03) 299.63,223.43 299.63,227.71
D11612: length 356.2
  L30_DIG w0.081: 303.91,210.63 305.19,210.63 306.05,211.49 313.45,211.49 317.37,207.58 338.87,207.58 353.31,222.02 365.46,222.02 373.49,230.05 373.49,259.63 398.55,284.69 398.55,299.86 410.33,311.64 410.33,394.06 409.21,395.18 322,395.18 321.37,394.54 321.37,392.49 D116.12
  L30_DIG w0.102: v1(301.63,211.03) 302.03,210.63 303.91,210.63
D11613: length 389.3
  L30_DIG w0.081: 303.91,208.23 314.28,208.23 316.58,205.94 354.76,205.94 364.65,215.83 399.62,215.83 403.4,219.6 403.4,298.95 415.41,310.96 415.41,394.75 412.66,397.5 321.3,397.5 D116.13
  L30_DIG w0.102: 303.91,208.23 302.03,208.23 v1(301.63,208.63)
D11614: length 394.1
  L32_DIG w0.081: 277.75,225.83 277.16,225.83 276.04,226.95 276.04,242.15 274.23,243.96 274.23,262.37 277.47,265.6 277.47,424.3 278.59,425.43 280.96,425.43 282.24,424.14 282.24,368.2 282.91,367.53 285.68,367.53 286.09,367.93 286.09,425.37 287.17,426.45 291.12,426.45 292.5,425.07 292.5,390.14 295.06,387.58 311.38,387.58 D116.14
  L32_DIG w0.102: 277.75,225.83 278.83,225.83 v1(279.23,225.43)
D11615: length 409
  L30_DIG w0.081: 303.91,206.63 313.21,206.63 317.2,202.63 391.68,202.63 406.58,217.54 406.58,295.68 420.48,309.58 420.48,395.21 415.7,399.99 318.71,399.99 D116.15
  L30_DIG w0.102: v1(301.63,207.03) 302.03,206.63 303.91,206.63
D11616: length 282.4
  L30_DIG w0.081: 303.91,220.23 304.94,220.23 305.63,220.93 314.03,220.93 316.59,223.49 316.59,243.3 317.46,244.17 317.46,258.62 322.53,263.69 348.35,263.69 350.36,265.7 350.36,377.42 353.73,380.79 365.69,380.79 367.8,382.9 367.8,386.06 366.16,387.7 313.34,387.7 D116.16
  L30_DIG w0.102: 303.91,220.23 302.03,220.23 v1(301.63,220.63)
D11701: length 212.3
  L07_DIG w0.081: 277.75,208.23 275.95,208.23 275.64,208.54 267.26,208.54 265.45,206.73 255.35,206.73 252.69,204.06 252.69,144.17 239.12,130.61 178.82,130.61 161.23,113.02 161.23,97.73 D117.01
  L07_DIG w0.102: v1(281.63,207.83) 281.23,208.23 277.75,208.23
D11702: length 225.6
  L03_DIG w0.096: 280.83,201.55 280.83,201.53 280.85,201.51 280.85,200.91 279.98,200.04 276.6,200.04 275.96,199.4 262.08,199.4 260.7,198.01 219.22,198.01 206.7,185.49 206.7,178.47 186.87,158.64 150.79,158.64 144.5,152.35 144.5,126.07 165.29,105.28 165.29,100.68 164.8,100.19 163.69,100.19 D117.02
  L03_DIG w0.102: 280.83,201.55 v1(280.83,202.23)
D11703: length 202.2
  L07_DIG w0.081: 277.75,207.43 276.22,207.43 275.64,206.85 267.7,206.85 263.93,203.08 260.49,203.08 256.04,198.64 256.04,154.38 255.43,153.76 255.43,144.69 237.08,126.34 180.66,126.34 166.26,111.94 166.26,97.68 D117.03
  L07_DIG w0.102: 277.75,207.43 281.23,207.43 v1(281.63,207.03)
D11704: length 225.6
  L03_DIG w0.096: D117.04 165.66,101.04 165.66,105.43 144.87,126.22 144.87,152.2 150.95,158.27 187.02,158.27 207.07,178.32 207.07,185.34 219.37,197.65 260.86,197.65 262.24,199.03 276.11,199.03 276.76,199.67 280.13,199.67 281.21,200.76 281.21,201.51 281.23,201.53 281.23,201.55
  L03_DIG w0.102: 281.23,201.55 281.23,202.63 v1(280.83,203.03)
D11705: length 327.7
  L07_DIG w0.081: 277.75,206.43 276.54,205.21 267.8,205.21 264.46,201.87 260.85,201.87 258.27,199.29 258.27,156.87 258.48,156.66 258.77,156.66 258.98,156.87 258.98,167.18 259.18,167.38 259.48,167.38 259.7,167.16 259.7,155.64 256.69,152.63 256.69,142.85 233.62,119.78 180.7,119.78 180.49,119.99 180.49,120.29 180.7,120.5 232.82,120.5 233.03,120.71 233.03,121 232.82,121.21 179.9,121.21 171.34,112.65 171.34,97.68 D117.05
  L07_DIG w0.102: 277.75,206.43 277.95,206.63 281.23,206.63 v1(281.63,206.23)
D11706: length 229.4
  L03_DIG w0.096: D117.06 174.79,101.13 174.79,136.32 212.43,173.96 212.43,179.17 219.84,186.58 262.51,186.58 264.02,185.07 264.02,181.65 262.49,180.12 253.48,180.12 251.97,178.61 251.97,174.95 253.9,173.03 270.59,173.03 271.51,173.95 271.51,177.28 274.43,180.2 274.43,191.33 276.61,193.51 276.61,195.47 277.79,196.65 282.01,196.65 282.41,197.05 282.41,200.26 282.85,200.69 282.85,201.51 282.83,201.53 282.83,201.55
  L03_DIG w0.102: v1(283.23,203.03) 282.83,202.63 282.83,201.55
D11707: length 273.7
  L07_DIG w0.081: 277.75,205.03 277.2,204.48 277.2,203.98 276.55,203.33 273.26,203.33 272.11,202.18 266.27,202.18 261.46,197.37 261.46,155.02 258.82,152.38 258.82,143.12 233.78,118.09 183.78,118.09 183.57,117.88 183.57,117.58 183.78,117.37 223.76,117.37 223.95,117.18 223.95,116.88 223.73,116.66 178.77,116.66 176.46,114.34 176.46,97.72 D117.07
  L07_DIG w0.102: 277.75,205.03 282.03,205.03 v1(282.43,205.43)
D11708: length 229.4
  L03_DIG w0.096: D117.08 176.69,100.17 175.45,100.17 175.16,100.46 175.16,136.17 212.8,173.81 212.8,179.02 220,186.21 262.36,186.21 263.65,184.92 263.65,181.8 262.34,180.49 253.32,180.49 251.6,178.77 251.6,174.8 253.74,172.66 270.74,172.66 271.88,173.8 271.88,177.13 274.8,180.04 274.8,191.17 276.98,193.36 276.98,195.32 277.94,196.28 282.16,196.28 282.78,196.9 282.78,200.1 283.21,200.54 283.21,201.51 283.23,201.53 283.23,201.55
  L03_DIG w0.102: 283.23,201.55 v1(283.23,202.23)
D11709: length 276.9
  L07_DIG w0.081: D117.09 181.49,97.67 181.49,111.28 184.62,114.41 229.57,114.41 229.78,114.2 229.78,113.91 229.57,113.7 186.76,113.7 186.54,113.48 186.54,113.18 186.74,112.98 230.96,112.98 261.08,143.1 261.08,152.75 262.62,154.28 262.62,185.22 264.09,186.69 264.09,197.53 266.55,199.98 275.53,199.98 276.57,201.02 283.08,201.02 283.6,201.55
  L07_DIG w0.102: v1(284.03,205.43) 283.63,205.03 283.63,201.58 283.6,201.55
D11710: length 276.9
  L03_DIG w0.096: 284.83,201.55 284.83,201.53 284.85,201.51 284.85,200.69 284.15,200 284.15,195.41 283.62,194.88 282.92,194.88 281.35,193.31 279.68,193.31 278.13,191.76 278.13,180.17 274.32,176.35 274.32,174.27 271.71,171.66 256.26,171.66 255.21,170.6 218.47,170.6 217.43,169.56 217.43,168.2 218.26,167.37 220.44,167.37 221.05,167.98 224.18,167.98 224.55,167.61 263.24,167.61 263.97,166.87 263.97,165.56 263.34,164.92 225.71,164.92 224.56,166.08 208.91,166.08 192.03,149.2 192.03,120.89 185.82,114.68 185.82,101.16 185.07,100.42 184.24,100.42 D117.10
  L03_DIG w0.102: 284.83,201.55 v1(284.83,202.23)
D11711: length 183.9
  L07_DIG w0.081: 285.04,201.55 283.56,200.07 277.24,200.07 276.26,199.09 267.13,199.09 264.97,196.92 264.97,185.88 263.6,184.52 263.6,143.24 230.4,110.04 191.41,110.04 186.64,105.27 186.64,97.74 D117.11
  L07_DIG w0.102: 285.04,201.55 285.23,201.74 285.23,205.73 285.33,205.83 286.03,205.83 v1(286.43,206.23)
D11712: length 276.9
  L03_DIG w0.096: 285.23,201.55 285.23,201.53 285.21,201.51 285.21,200.54 284.52,199.84 284.52,195.26 283.77,194.51 283.07,194.51 281.5,192.94 279.83,192.94 278.5,191.61 278.5,180.02 274.69,176.2 274.69,174.12 271.86,171.29 256.42,171.29 255.36,170.23 218.62,170.23 217.8,169.41 217.8,168.36 218.41,167.74 220.29,167.74 220.89,168.35 224.33,168.35 224.7,167.98 263.39,167.98 264.34,167.03 264.34,165.4 263.49,164.55 225.56,164.55 224.4,165.71 209.06,165.71 192.4,149.05 192.4,120.74 186.18,114.53 186.18,100.84 D117.12
  L03_DIG w0.102: 285.23,201.55 285.23,202.63 v1(284.83,203.03)
D11713: length 173.1
  L07_DIG w0.081: 286.03,201.55 286.03,201.16 284.54,199.67 284.54,198.7 283.88,198.04 279.34,198.04 278.93,197.63 276.86,197.63 274.66,195.43 274.66,190.85 271.23,187.42 271.23,182.02 268.71,179.5 268.71,156.32 265.88,153.49 265.88,142.26 230.95,107.33 195.74,107.33 191.82,103.42 191.82,97.84 D117.13
  L07_DIG w0.102: 286.03,201.55 286.03,205.03 v1(286.43,205.43)
D11714: length 229
  L03_DIG w0.096: 286.83,201.55 286.83,201.53 286.85,201.51 286.85,200.49 287.71,199.62 287.71,193.73 287.19,193.22 283.26,193.22 280.99,190.94 280.99,180.09 278.39,177.49 278.39,175.79 272.11,169.5 272.11,164.27 269.78,161.94 228.04,161.94 227.06,160.96 227.06,158.86 228.56,157.36 251.21,157.36 251.81,156.76 251.81,155.87 251.24,155.3 208.92,155.3 194.88,141.25 194.88,100.9 D117.14
  L03_DIG w0.102: v1(287.23,203.03) 286.83,202.63 286.83,201.55
D11715: length 168.9
  L07_DIG w0.081: D117.15 196.65,97.59 196.65,102.13 198.86,104.35 230.15,104.35 268,142.2 268,153.24 269.57,154.81 269.57,170.35 271.53,172.31 271.53,177.27 274.02,179.77 274.02,187.81 275.67,189.46 275.67,194.73 277.54,196.6 283.78,196.6 285.97,198.79 285.97,199.84 286.83,200.7 286.83,201.55
  L07_DIG w0.102: v1(287.23,205.43) 286.83,205.03 286.83,201.55
D11716: length 229
  L03_DIG w0.096: 287.23,201.55 287.23,201.53 287.21,201.51 287.21,200.64 288.08,199.78 288.08,193.58 287.34,192.85 283.41,192.85 281.35,190.79 281.35,179.93 278.76,177.34 278.76,175.63 272.47,169.35 272.47,164.11 269.93,161.57 228.19,161.57 227.43,160.81 227.43,159.01 228.71,157.73 251.36,157.73 252.18,156.91 252.18,155.72 251.39,154.93 209.07,154.93 195.24,141.1 195.24,101.02 195.82,100.44 196.74,100.44 D117.16
  L03_DIG w0.102: 287.23,201.55 v1(287.23,202.23)
D11801: length 230.1
  L09_DIG w0.081: 287.63,201.55 287.63,200.47 286.49,199.33 286.49,193.05 285.73,192.3 283.3,192.3 281.72,190.72 281.72,179.44 280.46,178.18 253.69,178.18 250.48,174.96 204.57,174.96 172.07,142.46 166.17,142.46 158.64,134.93 158.64,77.58 D118.01
  L09_DIG w0.102: v1(288.03,204.63) 287.63,204.23 287.63,201.55
D11802: length 433.8
  L05_DIG w0.079: D118.02 165.09,81.27 165.09,81.51 164.33,82.27 158.24,82.27 156.95,83.57 156.95,93.74 146.69,104 112.59,104 105.29,111.3 105.29,119.35 103.22,121.42 97.32,121.42 95.18,119.28 95.18,109.24 92.76,106.83 87.72,106.83 84.64,109.92 84.64,218.65 89.2,223.21 254.9,223.21 257.26,220.84 265.99,220.84 267.29,219.54 275.65,219.54 276.94,220.83 277.41,220.83
  L05_DIG w0.102: v1(280.83,220.63) 280.43,221.03 277.89,221.03 277.69,220.83 277.41,220.83
D11803: length 229.1
  L09_DIG w0.081: D118.03 163.95,77.35 163.95,137.06 167.8,140.91 173.18,140.91 204.9,172.63 227.24,172.63 227.65,173.04 250.39,173.04 251.5,171.93 277.56,171.93 282.63,177.01 282.63,190.13 283.97,191.46 286.43,191.46 287.67,192.7 287.67,199.71 288.43,200.47 288.43,201.55
  L09_DIG w0.102: 288.43,201.55 288.43,204.23 v1(288.83,204.63)
D11804: length 433.8
  L05_DIG w0.079: 277.41,220.45 277.1,220.45 275.8,219.16 267.14,219.16 265.83,220.46 257.11,220.46 254.74,222.83 89.36,222.83 85.02,218.49 85.02,110.08 87.88,107.21 92.6,107.21 94.8,109.4 94.8,119.44 97.16,121.8 103.38,121.8 105.67,119.51 105.67,111.46 112.75,104.38 146.85,104.38 157.33,93.89 157.33,83.73 158.4,82.66 164.49,82.66 165.48,81.67 165.48,80.9 D118.04
  L05_DIG w0.102: v1(281.63,220.63) 281.23,220.23 277.89,220.23 277.69,220.43 277.43,220.43 277.41,220.45
D11805: length 222.2
  L09_DIG w0.081: 289.23,201.55 289.23,200.31 288.29,199.36 288.29,192.14 287.35,191.2 287.35,190.03 285.75,188.42 285.75,177.89 278.78,170.92 225.84,170.92 225.28,170.36 204.37,170.36 172.97,138.96 172.97,137.4 171.68,136.11 171.68,134.63 168.96,131.91 168.96,77.42 D118.05
  L09_DIG w0.102: 289.23,201.55 289.23,204.23 v1(289.63,204.63)
D11806: length 314.6
  L05_DIG w0.079: 277.75,218.63 277.73,218.63 277.52,218.42 276.74,218.42 276.1,217.78 261.53,217.78 260.84,217.09 249.05,217.09 238.33,206.37 238.33,156.95 237.66,156.28 236.67,156.28 236.04,156.91 236.04,204.85 234.65,206.24 232.07,206.24 230.57,204.75 230.57,141.95 200.19,111.56 184.37,111.56 176.34,103.53 176.34,83.37 174.4,81.43 174.4,80.42 D118.06
  L05_DIG w0.102: v1(281.63,218.23) 281.23,218.63 277.75,218.63
D11807: length 221.8
  L09_DIG w0.081: D118.07 174.06,77.4 174.06,136.59 191.58,154.11 267.92,154.11 279.95,166.15 279.95,170.65 289,179.7 289,193.16 289.52,193.68 289.52,199.46 290.03,199.96 290.03,201.55
  L09_DIG w0.102: 290.03,201.55 290.03,204.23 v1(290.43,204.63)
D11808: length 314.6
  L05_DIG w0.079: D118.08 176.41,80.13 174.9,80.13 174.78,80.25 174.78,81.27 176.73,83.21 176.73,103.37 184.53,111.18 200.35,111.18 230.96,141.79 230.96,204.59 232.23,205.86 234.49,205.86 235.66,204.69 235.66,156.75 236.51,155.9 237.82,155.9 238.71,156.79 238.71,206.21 249.21,216.71 261,216.71 261.69,217.4 276.26,217.4 276.9,218.04 277.52,218.04 277.73,217.83 277.75,217.83
  L05_DIG w0.102: v1(280.83,218.23) 280.43,217.83 277.75,217.83
D11809: length 203.3
  L09_DIG w0.081: 290.83,201.55 290.83,199.95 290,199.12 290,179.12 281.55,170.67 281.55,165.86 267.88,152.19 267.88,146.71 255.68,134.51 208,134.51 179.09,105.6 179.09,77.45 D118.09
  L09_DIG w0.102: v1(291.23,204.63) 290.83,204.23 290.83,201.55
D11810: length 314.6
  L05_DIG w0.079: D118.10 184.41,80.27 184.41,81.42 186.37,83.39 186.37,102.25 188.13,104 201.1,104 208.28,96.83 208.28,53.6 209.99,51.9 222.95,51.9 224.08,53.02 224.08,129.41 235.87,141.21 235.87,150.27 243.82,158.21 243.82,206.31 250.2,212.7 259.53,212.7 262.84,216.01 275.84,216.01 276.66,216.82 277.52,216.82 277.73,217.03 277.75,217.03
  L05_DIG w0.102: 277.75,217.03 281.23,217.03 v1(281.63,216.63)
D11811: length 202.2
  L09_DIG w0.081: D118.11 184.22,77.4 184.22,105.42 210.61,131.81 254.92,131.81 270.34,147.23 270.34,151.59 282.63,163.88 282.63,166.89 290.27,174.53 291.36,174.53 291.77,174.95 291.77,176.98 294.06,179.28 294.06,189.72 291.63,192.16 291.63,201.55
  L09_DIG w0.102: 291.63,201.55 291.63,204.23 v1(292.03,204.63)
D11812: length 314.6
  L05_DIG w0.079: D118.12 186.71,79.99 185.43,79.99 184.79,80.63 184.79,81.26 186.76,83.23 186.76,102.09 188.29,103.62 200.94,103.62 207.9,96.67 207.9,53.44 209.83,51.51 223.11,51.51 224.46,52.86 224.46,129.25 236.26,141.05 236.26,150.11 244.2,158.06 244.2,206.15 250.36,212.31 259.68,212.31 263,215.63 276,215.63 276.81,216.44 277.52,216.44 277.73,216.23 277.75,216.23
  L05_DIG w0.102: v1(280.83,216.63) 280.43,216.23 277.75,216.23
